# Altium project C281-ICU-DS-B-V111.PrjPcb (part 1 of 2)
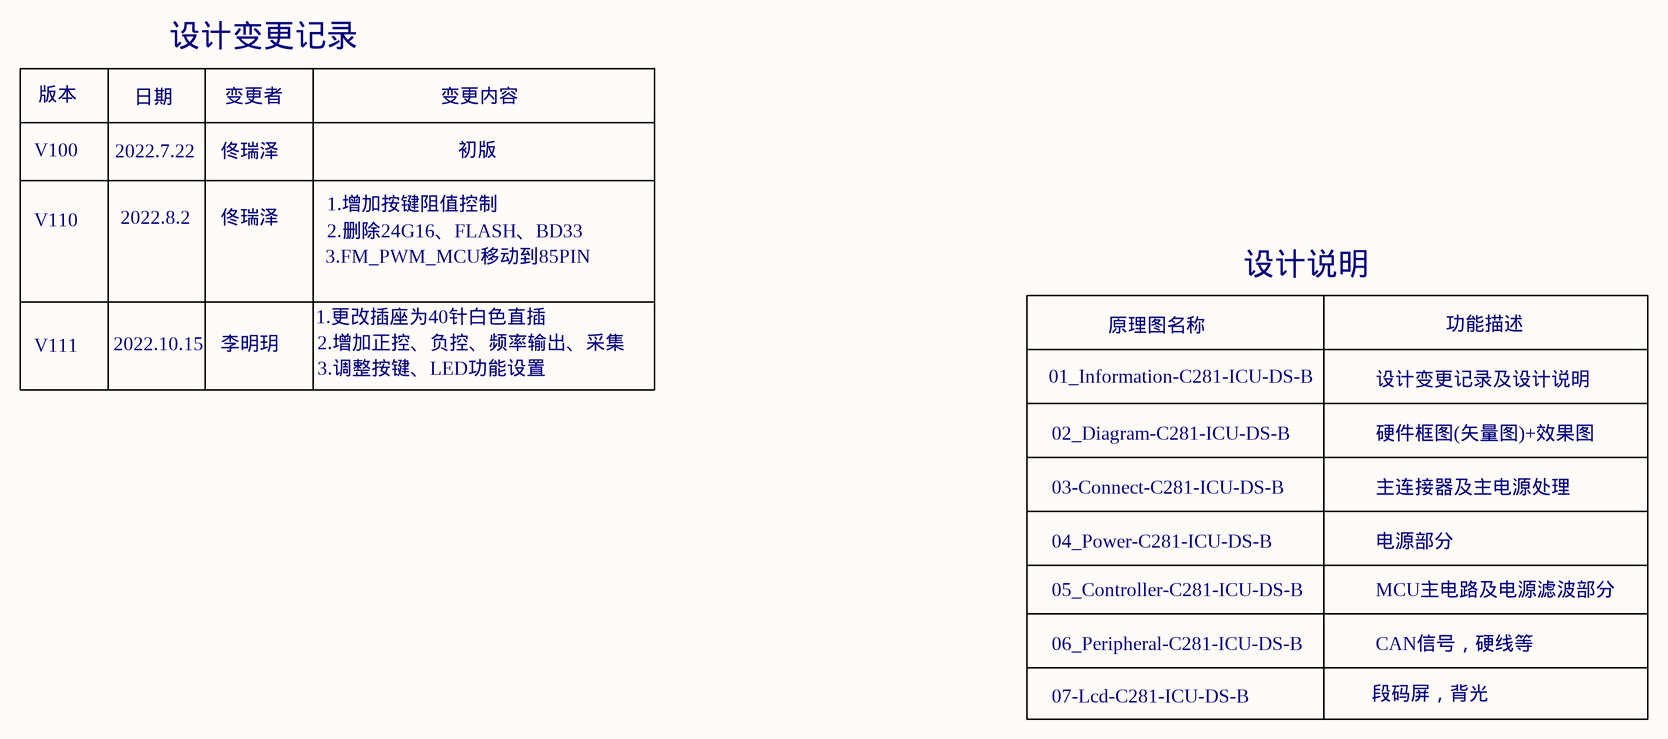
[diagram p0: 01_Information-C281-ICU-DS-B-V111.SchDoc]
7 sheets, 468 parts. Net scope: global (net labels, ports and power ports of the same name join across sheets).
Board file: C281-ICU-DS-B-V111.PcbDoc
Sheets:
  01_Information-C281-ICU-DS-B-V111.SchDoc
  02_Diagram-C281-ICU-DS-B-V111.SchDoc
  03_Connect-C281-ICU-DS-B-V111.SchDoc
  04_Power-C281-ICU-DS-B-V111.SchDoc
  05_Controller-C281-ICU-DS-B-V111.SchDoc
  06_Peripheral-C281-ICU-DS-B-V111.SchDoc
  07_Lcd-C281-ICU-DS-B-V111.SchDoc

## Sheet 01_Information-C281-ICU-DS-B-V111.SchDoc: C281-ICU-DS-B-V100
size A3; Date: 2022/07/22; DrawnBy: 佟瑞泽; DocumentNumber: 1; Revision: V100; SheetNumber: 1; SheetTotal: 7

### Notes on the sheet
- 设计变更记录
- 版本
- 日期
- 变更者
- 变更内容
- V100
- 2022.7.22
- 佟瑞泽
- 1.增加按键阻值控制
- 初版
- V110
- 2022.8.2
- 3.FM_PWM_MCU移动到85PIN
- 2.删除24G16、FLASH、BD33
- 设计说明
- 1.更改插座为40针白色直插
- 2.增加正控、负控、频率输出、采集
- 原理图名称
- 功能描述
- V111
- 2022.10.15
- 李明玥
- 3.调整按键、LED功能设置
- 01_Information-C281-ICU-DS-B
- 设计变更记录及设计说明
- 02_Diagram-C281-ICU-DS-B
- 硬件框图(矢量图)+效果图
- 03-Connect-C281-ICU-DS-B
- 04_Power-C281-ICU-DS-B
- 主连接器及主电源处理
- 电源部分
- 05_Controller-C281-ICU-DS-B
- MCU主电路及电源滤波部分
- 06_Peripheral-C281-ICU-DS-B
- CAN信号，硬线等
- 07-Lcd-C281-ICU-DS-B
- 段码屏，背光

## Sheet 02_Diagram-C281-ICU-DS-B-V111.SchDoc: C281-ICU-DS-B-V100
size A4; Date: 2022/07/22; DrawnBy: 佟瑞泽; DocumentNumber: 2; Revision: V100; SheetNumber: 2; SheetTotal: 7

## Sheet 03_Connect-C281-ICU-DS-B-V111.SchDoc: C281-ICU-DS-B-V100
size A4; Date: 2022/07/22; DrawnBy: 佟瑞泽; DocumentNumber: 3; Revision: V100; SheetNumber: 3; SheetTotal: 7
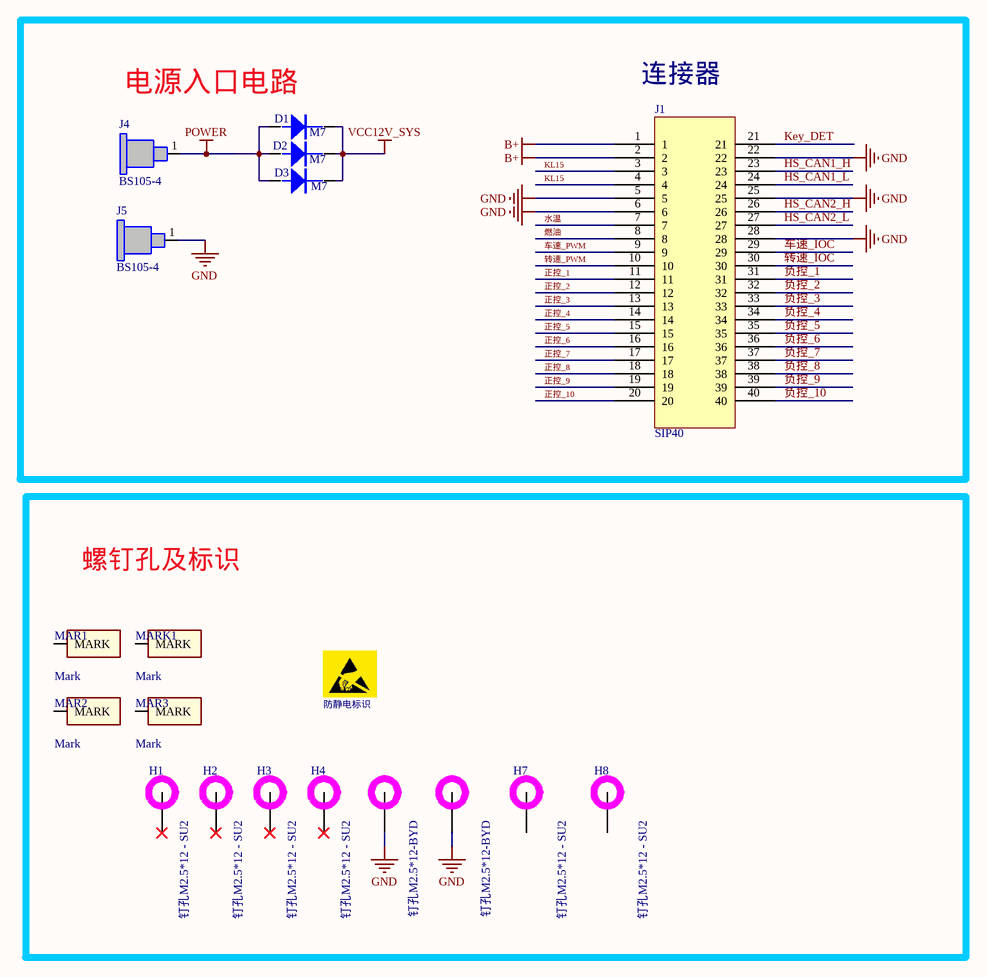
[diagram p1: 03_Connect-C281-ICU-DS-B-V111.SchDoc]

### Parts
D1  M7  [DO-214AC]
D2  M7  [DO-214AC]
D3  M7  [DO-214AC]
ESD1  ESD防静电标识  [ESD]  (value not drawn)  (no BOM)
H1  钉孔M2.5*12 - SU2  [钉孔M2.5*12 - SU2]  (no BOM)
H2  钉孔M2.5*12 - SU2  [钉孔M2.5*12 - SU2]  (no BOM)
H3  钉孔M2.5*12 - SU2  [钉孔M2.5*12 - SU2]  (no BOM)
H4  钉孔M2.5*12 - SU2  [钉孔M2.5*12 - SU2]  (no BOM)
H5  钉孔M2.5*12-BYD  [钉孔M2.5*12 - BYD]  (no BOM)
H6  钉孔M2.5*12-BYD  [钉孔M2.5*12 - BYD]  (no BOM)
H7  钉孔M2.5*12 - SU2  [钉孔M2.5*12 - SU2]  (no BOM)
H8  钉孔M2.5*12 - SU2  [钉孔M2.5*12 - SU2]  (no BOM)
J1  SIP40  [40P插座（白）]
J4  value BS105-4  [DIP-4MM]  (hidden comment: BS105-4-DIP)
J5  value BS105-4  [DIP-4MM]  (hidden comment: BS105-4-DIP)
MAR1  Mark  [MARK]  (no BOM)
MAR2  Mark  [MARK]  (no BOM)
MAR3  Mark  [MARK]  (no BOM)
MARK1  Mark  [MARK]  (no BOM)

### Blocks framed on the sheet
电源入口电路: D1-D3 J1 J4 J5
螺钉孔及标识: ESD1 H1-H8 MAR1-MAR3 MARK1

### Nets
B+: J1.1 J1.2
GND: H5.1 H6.1 J1.5 J1.6 J1.22 J1.25 J1.28 J5.1
KL15: J1.3 J1.4
POWER: D1.1 D2.1 D3.1 J4.1
VCC12V_SYS: D1.2 D2.2 D3.2
HS_CAN1_H: J1.23
HS_CAN1_L: J1.24
HS_CAN2_H: J1.26
HS_CAN2_L: J1.27
Key_DET: J1.21
正控_1: J1.11
正控_2: J1.12
正控_3: J1.13
正控_4: J1.14
正控_5: J1.15
正控_6: J1.16
正控_7: J1.17
正控_8: J1.18
正控_9: J1.19
正控_10: J1.20
水温: J1.7
燃油: J1.8
负控_1: J1.31
负控_2: J1.32
负控_3: J1.33
负控_4: J1.34
负控_5: J1.35
负控_6: J1.36
负控_7: J1.37
负控_8: J1.38
负控_9: J1.39
负控_10: J1.40
车速_IOC: J1.29
车速_PWM: J1.9
转速_IOC: J1.30
转速_PWM: J1.10

Not connected (* = marked no-connect by the designer): H1 1*; H2 1*; H3 1*; H4 1*; H7 1; H8 1; MAR1 1(MARK); MAR2 1(MARK); MAR3 1(MARK); MARK1 1(MARK)

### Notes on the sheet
- 连接器

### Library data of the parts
D1-D3 = M7: Diode,Vr=1000V,If=1.0A,Vf=1.1V,DO-214AC,M7,5.26*2.79*0.9mm; Part Number: 30307015; Manufacture 1: 深圳西龙; 代理/分销商: 深圳市长江电子有限公司
ESD1 = ESD防静电标识: 防静电标识
H1-H4 H7 H8 = 钉孔M2.5*12 - SU2: 适配M2.5*12螺钉
H5 H6 = 钉孔M2.5*12-BYD: 适配 M2.5*12 螺钉(钉帽直径6mm)
J1 = SIP40: Connector,单排针,PITCH=2.54mm,40PIN,DIP,直插,立式; Manufacture 1 P/N: 插座40针直; Part Number: 30401004; 代理/分销商: 深圳市国天电子股份有限公司
J4 J5 = BS105-4-DIP: Connector,4mm香蕉插头插座,H=28mm,DIP
MAR1-MAR3 MARK1 = Mark: MARK点

## Sheet 04_Power-C281-ICU-DS-B-V111.SchDoc: C281-ICU-DS-B-V100
size A4; Date: 2022/07/22; DrawnBy: 佟瑞泽; DocumentNumber: 4; Revision: V100; SheetNumber: 4; SheetTotal: 7
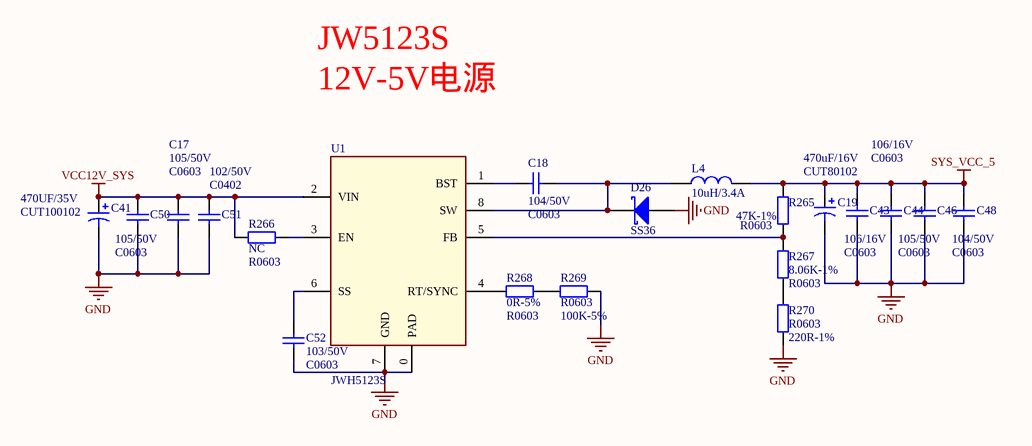
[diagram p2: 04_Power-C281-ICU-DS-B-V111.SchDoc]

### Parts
C17  value 105/50V  [C0603]  (hidden comment: 105-50V)
C18  value 104/50V  [C0603]  (hidden comment: 104)
C19  value 470uF/16V  [CUT80102]  (hidden comment: 470uF-16V)
C41  value 470UF/35V  [CUT100102]  (hidden comment: 470uF-35V)
C43  value 106/16V  [C0603]  (hidden comment: 106-16V)
C44  value 106/16V  [C0603]  (hidden comment: 106-16V)
C46  value 105/50V  [C0603]  (hidden comment: 105-50V)
C48  value 104/50V  [C0603]  (hidden comment: 104)
C50  value 105/50V  [C0603]  (hidden comment: 105-50V)
C51  value 102/50V  [C0402]  (hidden comment: 102-50V)
C52  value 103/50V  [C0603]  (hidden comment: 103)
D26  SS36  [DO-214AB]
L4  value 10uH/3.4A  [VLS6045EX]  (hidden comment: 6045EX-100M-H)
R265  value 47K-1%  [R0603]  (hidden comment: 47K-J)
R266  NC  [R0603]
R267  value 8.06K-1%  [R0603]  (hidden comment: 8.06K-J)
R268  value 0R-5%  [R0603]  (hidden comment: 0R)
R269  value 100K-5%  [R0603]  (hidden comment: 100K)
R270  value 220R-1%  [R0603]  (hidden comment: 220R-J)
U1  JWH5123S  [ESOP8]

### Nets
GND: C17.1 C19.2 C41.2 C43.1 C44.1 C46.1 C48.1 C50.1 C51.1 C52.1 D26.1(A) R269.2 R270.1 U1.0(PAD) U1.7(GND)
SYS_VCC_5: C19.1 C43.2 C44.2 C46.2 C48.2 L4.2 R265.2
VCC12V_SYS: C17.2 C41.1 C50.2 C51.2 R266.1 U1.2(VIN)
NetC18_1: C18.1 D26.2(K) L4.1 U1.8(SW)
NetC18_2: C18.2 U1.1(BST)
NetC52_2: C52.2 U1.6(SS)
NetR265_1: R265.1 R267.2 U1.5(FB)
NetR266_2: R266.2 U1.3(EN)
NetR267_1: R267.1 R270.2
NetR268_1: R268.1 U1.4(RT/SYNC)
NetR268_2: R268.2 R269.1

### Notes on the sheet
- 12V-5V电源
- JW5123S

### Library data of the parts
C17 C46 C50 = C105-50V-C0603-X: CAP,105,50V,10%,C0603; Part Number: 30305198; Manufacture 1: YAGEO; Manufacture 1 P/N: CL10A105KB8NNNC; 代理/分销商: 厦门信和达电子有限公司; 元件名称: 贴片电容105-0603-50V X
C18 C48 = C104-50V-C0603-X: CAP,104,50V,10%,,C0603; Part Number: 30305248; Manufacture 1 P/N: CC0603KRX7R9BB104; 代理/分销商: 厦门信和达电子有限公司; 元件名称: 贴片电容104-0603-50V X
C19 = C470UF-16V-CUT80102: ECAP,470uF,16V,20%,φ8x10.2mm,SMD; Part Number: 30311002; Manufacture 1: KS; Manufacture 1 P/N: CS16V470UF; 代理/分销商: 北京圣基工贸公司/广东东联盛科技有限公司/东莞市柯森奥泰科技有限公司; 元件名称: 贴片电解16V470
C41 = C470uF-35V-CUT100102: ECAP,470uF,35V,20%,φ10x10.2mm,SMD; Part Number: 30311004; Manufacture 1: KS; Manufacture 1 P/N: CS35V470UF; 代理/分销商: 北京圣基工贸公司/广东东联盛科技有限公司/东莞市柯森奥泰科技有限公司; 元件名称: 贴片电解35V470
C43 C44 = C106-16V-C0603-X: CAP,106,16V,20%,C0603; Part Number: 30305207; Manufacture 1: YAGEO; Manufacture 1 P/N: CC0603MRX5R7BB106; 代理/分销商: 厦门信和达电子有限公司; 元件名称: 贴片电容106-0603-16V X
C51 = C102-50V-C0402-X: CAP,102,50V,10%,C0402; Part Number: 30305215; Manufacture 1: YAGEO; Manufacture 1 P/N: CC0402KRX7R9BB102; 代理/分销商: 厦门信和达电子有限公司; 元件名称: 贴片电容102-0402-50V X
C52 = C103-50V-C0603-X: CAP,103,50V,10%,C0603; Part Number: 30305245; Manufacture 1: YAGEO; Manufacture 1 P/N: CC0603KRX7R9BB103; 代理/分销商: 厦门信和达电子有限公司; 元件名称: 贴片电容103-0603-50V X
D26 = SS36: Diode,Vr=60V,If=3A,Vf=0.75V,DO-214AB,SS36,6.22*8.13*2.62mm; Part Number: 30307090; Manufacture 1: GENERAL SEMICONDUCTOR; 代理/分销商: 四平市吉华高新技术有限公司; 元件名称: 肖特基二极管SS36
L4 = VLS6045EX-100M-H: Inductor,10uH±20%,3.9AIsat),3.4A(Itemp),6.3*6*4.5mm; Part Number: 30310059; Manufacture 1: TDK; 代理/分销商: 创思（北京）电子技术有限公司; 元件名称: VLS6045EX-100M-H  10UH电感（车规级）
R265 = R47K_0603_1%: RES,47K,1/10W,1%,R0603; Part Number: 30304413; Manufacture 1: 风华高科FH; Manufacture 1 P/N: RS03K4702FT; 代理/分销商: 四平市吉华高新技术有限公司; 元件名称: 贴片电阻47KΩ-精密-0603
R266 = R_NC_0603: RES,R0603; 元件名称: 贴片电阻NC-0603
R267 = R8.06K_0603_1%_X: RES,8.06K,1/10W,1%,R0603; Part Number: 30304398; Manufacture 1: YAGEO; Manufacture 1 P/N: RC0603FR-078K06L; 代理/分销商: 厦门信和达电子有限公司; 元件名称: 贴片电阻8.06K-0603-精密 X
R268 = R0R_0603_5%_X: RES,0R,1/10W,5%,R0603; Part Number: 30304421; Manufacture 1: YAGEO; Manufacture 1 P/N: RC0603JR-070RL; 代理/分销商: 厦门信和达电子有限公司; 元件名称: 贴片电阻0Ω-0603 X
R269 = R100K_0603_5%_X: RES,100K,1/10W,5%,R0603; Part Number: 30304410; Manufacture 1: YAGEO; Manufacture 1 P/N: RC0603JR-07100KL; 代理/分销商: 厦门信和达电子有限公司; 元件名称: 贴片电阻100K-0603 X
R270 = R220R_0603_1%_X: RES,220R,1/10W,1%,R0603; Part Number: 30304392; Manufacture 1: YAGEO; Manufacture 1 P/N: RC0603FR-07220RL; 代理/分销商: 厦门信和达电子有限公司; 元件名称: 贴片电阻220Ω-0603-精密 X
U1 = JWH5123S: IC,JWH5123S,DCDC,ESOP-8,6x4.9x1.5mm,-40~125℃; Part Number: 30301464; Manufacture 1: JWJOULWATT; Manufacture 1 P/N: JWH5123SESOP#TRPBF; 备注: 电源芯片JW5123; 代理/分销商: 大联大商贸有限公司

## Sheet 05_Controller-C281-ICU-DS-B-V111.SchDoc: C281-ICU-DS-B-V100
size A2; Date: 2022/07/22; DrawnBy: 佟瑞泽; Organization: Protel International P/L; DocumentNumber: 5; Revision: V100; SheetNumber: 5; SheetTotal: 7
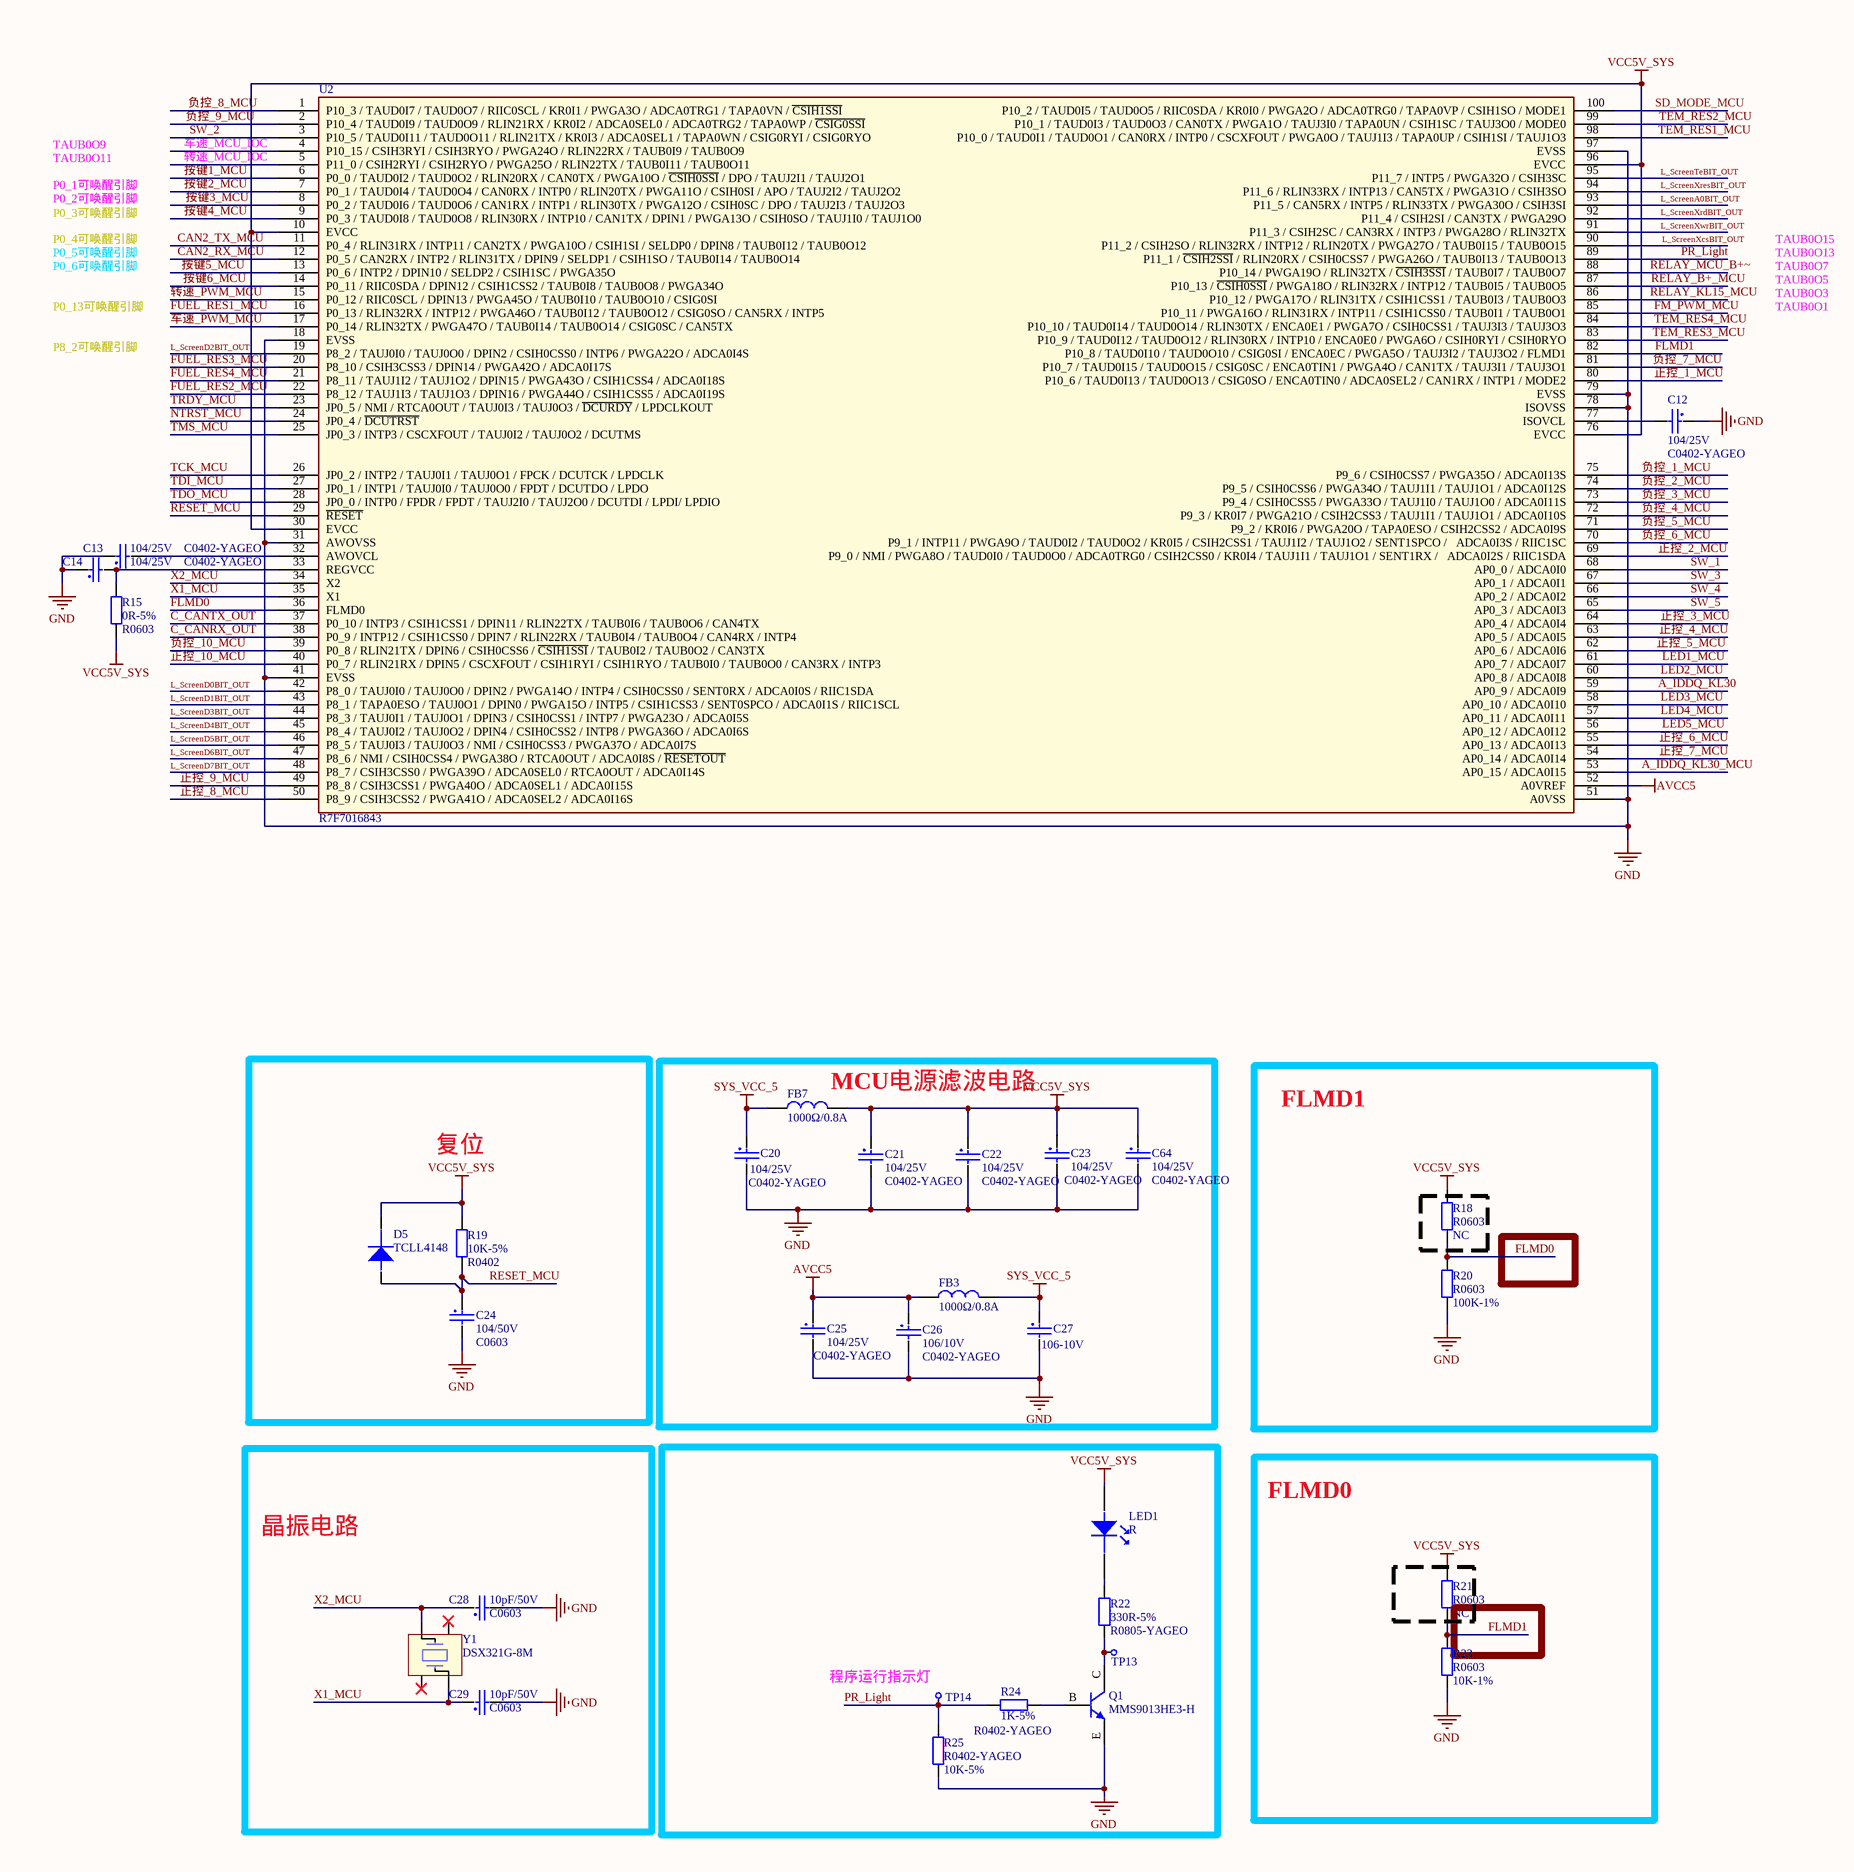
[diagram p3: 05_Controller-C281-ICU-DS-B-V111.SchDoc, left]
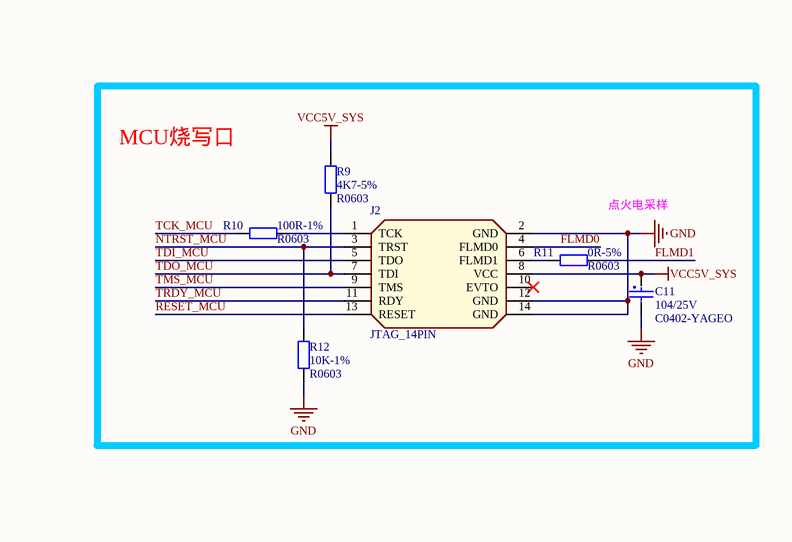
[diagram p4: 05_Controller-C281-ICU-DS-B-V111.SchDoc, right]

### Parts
C11  value 104/25V  [C0402-YAGEO]  (hidden comment: 104-25V)
C12  value 104/25V  [C0402-YAGEO]  (hidden comment: 104-25V)
C13  value 104/25V  [C0402-YAGEO]  (hidden comment: 104-25V)
C14  value 104/25V  [C0402-YAGEO]  (hidden comment: 104-25V)
C20  value 104/25V  [C0402-YAGEO]  (hidden comment: 104-25V)
C21  value 104/25V  [C0402-YAGEO]  (hidden comment: 104-25V)
C22  value 104/25V  [C0402-YAGEO]  (hidden comment: 104-25V)
C23  value 104/25V  [C0402-YAGEO]  (hidden comment: 104-25V)
C24  value 104/50V  Footprint: C0603  [C0603-YAGEO]  (hidden comment: 104)
C25  value 104/25V  [C0402-YAGEO]  (hidden comment: 104-25V)
C26  value 106/10V  [C0402-YAGEO]  (hidden comment: 106-10V)
C27  106-10V  [C0402-YAGEO]
C28  value 10pF/50V  [C0603]  (hidden comment: 10pF)
C29  value 10pF/50V  [C0603]  (hidden comment: 10pF)
C64  value 104/25V  [C0402-YAGEO]  (hidden comment: 104-25V)
D5  value TCLL4148  [4148-A]  (hidden comment: 4148)
FB3  value 1000Ω/0.8A  [BLM18PG600SH1]  (hidden comment: 1000@100MHz)
FB7  value 1000Ω/0.8A  [BLM18PG600SH1]  (hidden comment: 1000@100MHz)
J2  value JTAG_14PIN  [JTAG-14PIN]  (hidden comment: JTAG_14)
LED1  R  [LED]
Q1  MMS9013HE3-H  [SOT-23]
R9  value 4K7-5%  Footprint: R0603  [R0603-YAGEO]  (hidden comment: 4K7)
R10  100R-1%  [R0603]
R11  value 0R-5%  Footprint: R0603  [R0603-YAGEO]  (hidden comment: 0R)
R12  value 10K-1%  Footprint: R0603  [R0603-YAGEO]  (hidden comment: 10K-J)
R15  value 0R-5%  [R0603]  (hidden comment: 0R)
R18  NC  [R0603]
R19  value 10K-5%  Footprint: R0402  [R0402-YAGEO]  (hidden comment: 10K)
R20  value 100K-1%  Footprint: R0603  [R0603-YAGEO]  (hidden comment: 100K-J)
R21  NC  [R0603]
R22  value 330R-5%  [R0805-YAGEO]  (hidden comment: 330R)
R23  value 10K-1%  Footprint: R0603  [R0603-YAGEO]  (hidden comment: 10K-J)
R24  value 1K-5%  [R0402-YAGEO]  (hidden comment: 1K)
R25  value 10K-5%  [R0402-YAGEO]  (hidden comment: 10K)
TP13  1.0测试点  [TP1.0]  (value not drawn)
TP14  1.0测试点  [TP1.0]  (value not drawn)
U2  R7F7016843  [P-LFQFP100]
Y1  value DSX321G-8M  [Crystal3225]  (hidden comment: 8M)

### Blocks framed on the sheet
MCU烧写口: C11 J2 R9-R12
复位: C24 D5 R19
MCU电源滤波电路: C20-C23 C25-C27 C64 FB3 FB7
FLMD1: R18 R20
晶振电路: C28 C29 Y1
程序运行指示灯: LED1 Q1 R22 R24 R25 TP13 TP14
FLMD0: R21 R23

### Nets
AVCC5: C25.1 C26.1 FB3.1 U2.52(A0VREF)
GND: C11.2 C12.1 C13.1 C14.1 C20.2 C21.2 C22.2 C23.2 C24.2 C25.2 C26.2 C27.2 C28.2 C29.2 C64.2 J2.2(GND) J2.12(GND) J2.14(GND) Q1.E R12.2 R20.1 R23.1 R25.1 U2.18(EVSS) U2.31(AWOVSS) U2.41(EVSS) U2.51(A0VSS) U2.78(ISOVSS) U2.79(EVSS) U2.97(EVSS)
SYS_VCC_5: C20.1 C27.1 FB3.2 FB7.1
VCC5V_SYS: C11.1 C21.1 C22.1 C23.1 C64.1 D5.2 FB7.2 J2.8(VCC) LED1.1 R9.1 R15.1 R18.2 R19.2 R21.2 U2.10(EVCC) U2.30(EVCC) U2.76(EVCC) U2.96(EVCC)
A_IDDQ_KL30: U2.59(AP0_9_/_ADCA0I9)
A_IDDQ_KL30_MCU: U2.53(AP0_15_/_ADCA0I15)
C_CANRX_OUT: U2.38(P0_9_/_INTP12_/_CSIH1CSS0_/_DPIN7_/_RLIN22RX_/_TAUB0I4_/_TAUB0O4_/_CAN4RX_/_INTP4)
C_CANTX_OUT: U2.37(P0_10_/_INTP3_/_CSIH1CSS1_/_DPIN11_/_RLIN22TX_/_TAUB0I6_/_TAUB0O6_/_CAN4TX)
CAN2_RX_MCU: U2.12(P0_5_/_CAN2RX_/_INTP2_/_RLIN31TX_/_DPIN9_/_SELDP1_/_CSIH1SO_/_TAUB0I14_/_TAUB0O14)
CAN2_TX_MCU: U2.11(P0_4_/_RLIN31RX_/_INTP11_/_CAN2TX_/_PWGA10O_/_CSIH1SI_/_SELDP0_/_DPIN8_/_TAUB0I12_/_TAUB0O12)
FLMD0: J2.4(FLMD0) R18.1 R20.2 U2.36(FLMD0)
FLMD1: R11.2 R21.1 R23.2 U2.82(P10_8_/_TAUD0I10_/_TAUD0O10_/_CSIG0SI_/_ENCA0EC_/_PWGA5O_/_TAUJ3I2_/_TAUJ3O2_/_FLMD1)
FM_PWM_MCU: U2.85(P10_11_/_PWGA16O_/_RLIN31RX_/_INTP11_/_CSIH1CSS0_/_TAUB0I1_/_TAUB0O1)
FUEL_RES1_MCU: U2.16(P0_13_/_RLIN32RX_/_INTP12_/_PWGA46O_/_TAUB0I12_/_TAUB0O12_/_CSIG0SO_/_CAN5RX_/_INTP5)
FUEL_RES2_MCU: U2.22(P8_12_/_TAUJ1I3_/_TAUJ1O3_/_DPIN16_/_PWGA44O_/_CSIH1CSS5_/_ADCA0I19S)
FUEL_RES3_MCU: U2.20(P8_10_/_CSIH3CSS3_/_DPIN14_/_PWGA42O_/_ADCA0I17S)
FUEL_RES4_MCU: U2.21(P8_11_/_TAUJ1I2_/_TAUJ1O2_/_DPIN15_/_PWGA43O_/_CSIH1CSS4_/_ADCA0I18S)
L_ScreenA0BIT_OUT: U2.93(P11_5_/_CAN5RX_/_INTP5_/_RLIN33TX_/_PWGA30O_/_CSIH3SI)
L_ScreenD0BIT_OUT: U2.42(P8_0_/_TAUJ0I0_/_TAUJ0O0_/_DPIN2_/_PWGA14O_/_INTP4_/_CSIH0CSS0_/_SENT0RX_/_ADCA0I0S_/_RIIC1SDA)
L_ScreenD1BIT_OUT: U2.43(P8_1_/_TAPA0ESO_/_TAUJ0O1_/_DPIN0_/_PWGA15O_/_INTP5_/_CSIH1CSS3_/_SENT0SPCO_/_ADCA0I1S_/_RIIC1SCL)
L_ScreenD2BIT_OUT: U2.19(P8_2_/_TAUJ0I0_/_TAUJ0O0_/_DPIN2_/_CSIH0CSS0_/_INTP6_/_PWGA22O_/_ADCA0I4S)
L_ScreenD3BIT_OUT: U2.44(P8_3_/_TAUJ0I1_/_TAUJ0O1_/_DPIN3_/_CSIH0CSS1_/_INTP7_/_PWGA23O_/_ADCA0I5S)
L_ScreenD4BIT_OUT: U2.45(P8_4_/_TAUJ0I2_/_TAUJ0O2_/_DPIN4_/_CSIH0CSS2_/_INTP8_/_PWGA36O_/_ADCA0I6S)
L_ScreenD5BIT_OUT: U2.46(P8_5_/_TAUJ0I3_/_TAUJ0O3_/_NMI_/_CSIH0CSS3_/_PWGA37O_/_ADCA0I7S)
L_ScreenD6BIT_OUT: U2.47(P8_6_/_NMI_/_CSIH0CSS4_/_PWGA38O_/_RTCA0OUT_/_ADCA0I8S_/_~{RESETOUT})
L_ScreenD7BIT_OUT: U2.48(P8_7_/_CSIH3CSS0_/_PWGA39O_/_ADCA0SEL0_/_RTCA0OUT_/_ADCA0I14S)
L_ScreenTeBIT_OUT: U2.95(P11_7_/_INTP5_/_PWGA32O_/_CSIH3SC)
L_ScreenXcsBIT_OUT: U2.90(P11_2_/_CSIH2SO_/_RLIN32RX_/_INTP12_/_RLIN20TX_/_PWGA27O_/_TAUB0I15_/_TAUB0O15)
L_ScreenXrdBIT_OUT: U2.92(P11_4_/_CSIH2SI_/_CAN3TX_/_PWGA29O)
L_ScreenXresBIT_OUT: U2.94(P11_6_/_RLIN33RX_/_INTP13_/_CAN5TX_/_PWGA31O_/_CSIH3SO)
L_ScreenXwrBIT_OUT: U2.91(P11_3_/_CSIH2SC_/_CAN3RX_/_INTP3_/_PWGA28O_/_RLIN32TX)
LED1_MCU: U2.61(AP0_7_/_ADCA0I7)
LED2_MCU: U2.60(AP0_8_/_ADCA0I8)
LED3_MCU: U2.58(AP0_10_/_ADCA0I10)
LED4_MCU: U2.57(AP0_11_/_ADCA0I11)
LED5_MCU: U2.56(AP0_12_/_ADCA0I12)
NTRST_MCU: J2.3(TRST) R12.1 U2.24(JP0_4_/_~{DCUTRST})
PR_Light: R24.2 R25.2 TP14.1 U2.89(P11_1_/_~{CSIH2SSI}_/_RLIN20RX_/_CSIH0CSS7_/_PWGA26O_/_TAUB0I13_/_TAUB0O13)
RELAY_B+_MCU: U2.87(P10_13_/_~{CSIH0SSI}_/_PWGA18O_/_RLIN32RX_/_INTP12_/_TAUB0I5_/_TAUB0O5)
RELAY_KL15_MCU: U2.86(P10_12_/_PWGA17O_/_RLIN31TX_/_CSIH1CSS1_/_TAUB0I3_/_TAUB0O3)
RELAY_MCU_B+~: U2.88(P10_14_/_PWGA19O_/_RLIN32TX_/_~{CSIH3SSI}_/_TAUB0I7_/_TAUB0O7)
RESET_MCU: C24.1 D5.1 J2.13(RESET) R19.1 U2.29(~{RESET})
SD_MODE_MCU: U2.100(P10_2_/_TAUD0I5_/_TAUD0O5_/_RIIC0SDA_/_KR0I0_/_PWGA2O_/_ADCA0TRG0_/_TAPA0VP_/_CSIH1SO_/_MODE1)
SW_1: U2.68(AP0_0_/_ADCA0I0)
SW_2: U2.3(P10_5_/_TAUD0I11_/_TAUD0O11_/_RLIN21TX_/_KR0I3_/_ADCA0SEL1_/_TAPA0WN_/_CSIG0RYI_/_CSIG0RYO)
SW_3: U2.67(AP0_1_/_ADCA0I1)
SW_4: U2.66(AP0_2_/_ADCA0I2)
SW_5: U2.65(AP0_3_/_ADCA0I3)
TCK_MCU: R10.1 U2.26(JP0_2_/_INTP2_/_TAUJ0I1_/_TAUJ0O1_/_FPCK_/_DCUTCK_/_LPDCLK)
TDI_MCU: J2.5(TDO) U2.27(JP0_1_/_INTP1_/_TAUJ0I0_/_TAUJ0O0_/_FPDT_/_DCUTDO_/_LPDO)
TDO_MCU: J2.7(TDI) R9.2 U2.28(JP0_0_/_INTP0_/_FPDR_/_FPDT_/_TAUJ2I0_/_TAUJ2O0_/_DCUTDI_/_LPDI/_LPDIO)
TEM_RES1_MCU: U2.98(P10_0_/_TAUD0I1_/_TAUD0O1_/_CAN0RX_/_INTP0_/_CSCXFOUT_/_PWGA0O_/_TAUJ1I3_/_TAPA0UP_/_CSIH1SI_/_TAUJ1O3)
TEM_RES2_MCU: U2.99(P10_1_/_TAUD0I3_/_TAUD0O3_/_CAN0TX_/_PWGA1O_/_TAUJ3I0_/_TAPA0UN_/_CSIH1SC_/_TAUJ3O0_/_MODE0)
TEM_RES3_MCU: U2.83(P10_9_/_TAUD0I12_/_TAUD0O12_/_RLIN30RX_/_INTP10_/_ENCA0E0_/_PWGA6O_/_CSIH0RYI_/_CSIH0RYO)
TEM_RES4_MCU: U2.84(P10_10_/_TAUD0I14_/_TAUD0O14_/_RLIN30TX_/_ENCA0E1_/_PWGA7O_/_CSIH0CSS1_/_TAUJ3I3_/_TAUJ3O3)
TMS_MCU: J2.9(TMS) U2.25(JP0_3_/_INTP3_/_CSCXFOUT_/_TAUJ0I2_/_TAUJ0O2_/_DCUTMS)
TRDY_MCU: J2.11(RDY) U2.23(JP0_5_/_NMI_/_RTCA0OUT_/_TAUJ0I3_/_TAUJ0O3_/_~{DCURDY}_/_LPDCLKOUT)
X1_MCU: C29.1 U2.35(X1) Y1.1
X2_MCU: C28.1 U2.34(X2) Y1.3
按键1_MCU: U2.6(P0_0_/_TAUD0I2_/_TAUD0O2_/_RLIN20RX_/_CAN0TX_/_PWGA10O_/_~{CSIH0SSI}_/_DPO_/_TAUJ2I1_/_TAUJ2O1)
按键2_MCU: U2.7(P0_1_/_TAUD0I4_/_TAUD0O4_/_CAN0RX_/_INTP0_/_RLIN20TX_/_PWGA11O_/_CSIH0SI_/_APO_/_TAUJ2I2_/_TAUJ2O2)
按键3_MCU: U2.8(P0_2_/_TAUD0I6_/_TAUD0O6_/_CAN1RX_/_INTP1_/_RLIN30TX_/_PWGA12O_/_CSIH0SC_/_DPO_/_TAUJ2I3_/_TAUJ2O3)
按键4_MCU: U2.9(P0_3_/_TAUD0I8_/_TAUD0O8_/_RLIN30RX_/_INTP10_/_CAN1TX_/_DPIN1_/_PWGA13O_/_CSIH0SO_/_TAUJ1I0_/_TAUJ1O0)
按键5_MCU: U2.13(P0_6_/_INTP2_/_DPIN10_/_SELDP2_/_CSIH1SC_/_PWGA35O)
按键6_MCU: U2.14(P0_11_/_RIIC0SDA_/_DPIN12_/_CSIH1CSS2_/_TAUB0I8_/_TAUB0O8_/_PWGA34O)
正控_1_MCU: U2.80(P10_6_/_TAUD0I13_/_TAUD0O13_/_CSIG0SO_/_ENCA0TIN0_/_ADCA0SEL2_/_CAN1RX_/_INTP1_/_MODE2)
正控_2_MCU: U2.69(P9_0_/_NMI_/_PWGA8O_/_TAUD0I0_/_TAUD0O0_/_ADCA0TRG0_/_CSIH2CSS0_/_KR0I4_/_TAUJ1I1_/_TAUJ1O1_/_SENT1RX_/___ADCA0I2S_/_RIIC1SDA)
正控_3_MCU: U2.64(AP0_4_/_ADCA0I4)
正控_4_MCU: U2.63(AP0_5_/_ADCA0I5)
正控_5_MCU: U2.62(AP0_6_/_ADCA0I6)
正控_6_MCU: U2.55(AP0_13_/_ADCA0I13)
正控_7_MCU: U2.54(AP0_14_/_ADCA0I14)
正控_8_MCU: U2.50(P8_9_/_CSIH3CSS2_/_PWGA41O_/_ADCA0SEL2_/_ADCA0I16S)
正控_9_MCU: U2.49(P8_8_/_CSIH3CSS1_/_PWGA40O_/_ADCA0SEL1_/_ADCA0I15S)
正控_10_MCU: U2.40(P0_7_/_RLIN21RX_/_DPIN5_/_CSCXFOUT_/_CSIH1RYI_/_CSIH1RYO_/_TAUB0I0_/_TAUB0O0_/_CAN3RX_/_INTP3)
负控_1_MCU: U2.75(P9_6_/_CSIH0CSS7_/_PWGA35O_/_ADCA0I13S)
负控_2_MCU: U2.74(P9_5_/_CSIH0CSS6_/_PWGA34O_/_TAUJ1I1_/_TAUJ1O1_/_ADCA0I12S)
负控_3_MCU: U2.73(P9_4_/_CSIH0CSS5_/_PWGA33O_/_TAUJ1I0_/_TAUJ1O0_/_ADCA0I11S)
负控_4_MCU: U2.72(P9_3_/_KR0I7_/_PWGA21O_/_CSIH2CSS3_/_TAUJ1I1_/_TAUJ1O1_/_ADCA0I10S)
负控_5_MCU: U2.71(P9_2_/_KR0I6_/_PWGA20O_/_TAPA0ESO_/_CSIH2CSS2_/_ADCA0I9S)
负控_6_MCU: U2.70(P9_1_/_INTP11_/_PWGA9O_/_TAUD0I2_/_TAUD0O2_/_KR0I5_/_CSIH2CSS1_/_TAUJ1I2_/_TAUJ1O2_/_SENT1SPCO_/___ADCA0I3S_/_RIIC1SC)
负控_7_MCU: U2.81(P10_7_/_TAUD0I15_/_TAUD0O15_/_CSIG0SC_/_ENCA0TIN1_/_PWGA4O_/_CAN1TX_/_TAUJ3I1_/_TAUJ3O1)
负控_8_MCU: U2.1(P10_3_/_TAUD0I7_/_TAUD0O7_/_RIIC0SCL_/_KR0I1_/_PWGA3O_/_ADCA0TRG1_/_TAPA0VN_/_~{CSIH1SSI})
负控_9_MCU: U2.2(P10_4_/_TAUD0I9_/_TAUD0O9_/_RLIN21RX_/_KR0I2_/_ADCA0SEL0_/_ADCA0TRG2_/_TAPA0WP_/_~{CSIG0SSI})
负控_10_MCU: U2.39(P0_8_/_RLIN21TX_/_DPIN6_/_CSIH0CSS6_/_~{CSIH1SSI}_/_TAUB0I2_/_TAUB0O2_/_CAN3TX)
车速_MCU_IOC: U2.4(P10_15_/_CSIH3RYI_/_CSIH3RYO_/_PWGA24O_/_RLIN22RX_/_TAUB0I9_/_TAUB0O9)
车速_PWM_MCU: U2.17(P0_14_/_RLIN32TX_/_PWGA47O_/_TAUB0I14_/_TAUB0O14_/_CSIG0SC_/_CAN5TX)
转速_MCU_IOC: U2.5(P11_0_/_CSIH2RYI_/_CSIH2RYO_/_PWGA25O_/_RLIN22TX_/_TAUB0I11_/_TAUB0O11)
转速_PWM_MCU: U2.15(P0_12_/_RIIC0SCL_/_DPIN13_/_PWGA45O_/_TAUB0I10_/_TAUB0O10_/_CSIG0SI)
NetC12_2: C12.2 U2.77(ISOVCL)
NetC13_2: C13.2 U2.32(AWOVCL)
NetC14_2: C14.2 R15.2 U2.33(REGVCC)
NetJ2_1: J2.1(TCK) R10.2
NetJ2_6: J2.6(FLMD1) R11.1
NetLED1_2: LED1.2 R22.2
NetQ1_B: Q1.B R24.1
NetQ1_C: Q1.C R22.1 TP13.1

Not connected (* = marked no-connect by the designer): J2 10(EVTO)*; Y1 2* 4*

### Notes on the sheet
- 点火电采样
- Labels drawn without touching a wire or pin: P0_1可唤醒引脚, P0_2可唤醒引脚, P0_3可唤醒引脚, P0_4可唤醒引脚, P0_5可唤醒引脚, P0_6可唤醒引脚, P0_13可唤醒引脚, P8_2可唤醒引脚, TAUB0O1, TAUB0O3, TAUB0O5, TAUB0O7, TAUB0O9, TAUB0O11, TAUB0O13, TAUB0O15

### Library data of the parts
C11-C14 C20-C23 C25 C64 = C104-25V-C0402-X: CAP,104,25V,10%,C0402; Part Number: 30305217; Manufacture 1: YAGEO; Manufacture 1 P/N: CC0402KRX7R8BB104; 代理/分销商: 厦门信和达电子有限公司
C24 = C104-50V-C0603-X: CAP,104,50V,10%,C0603; Part Number: 30305248; Manufacture 1: YAGEO; Manufacture 1 P/N: CC0603KRX7R9BB104; 代理/分销商: 厦门信和达电子有限公司
C26 C27 = C106-10V-C0402-X: CAP,106,10V,10%,C0402; Part Number: 30305214; Manufacture 1: YAGEO; Manufacture 1 P/N: CC0402MRX5R6BB106; 代理/分销商: 厦门信和达电子有限公司
C28 C29 = C10pF-50V-C0603-X: CAP,10pF,50V,5%,C0603; Part Number: 30305257; Manufacture 1: YAGEO; Manufacture 1 P/N: CC0603JRNPO9BN100; 代理/分销商: 厦门信和达电子有限公司
D5 = 1N4148: Diode,If=10mA@Vf=1.0V,Wiv=75V,DO213AC,TCLL4148; Part Number: 30307014; Manufacture 1: TAK CHEONG; 代理/分销商: 深圳市长江电子有限公司
FB3 FB7 = 1000Ω/0.8A-AEC-Q200: Bead,1000Ω@100MHz,25%,0.8A,1.6x0.8x0.8mm; Part Number: 30319012; Manufacture 1: TDK; Manufacture 1 P/N: MPZ1608S102ATD25; 代理/分销商: 创思（北京）电子技术有限公司
J2 = JTAG_14PIN: Connector,双排针,PITCH=2.54mm,14PIN,SMD
LED1 = LED-R: LED,普通红; Part Number: 30303001
Q1 = MMS9013HE3-H: NPN,Vcbo=40V,Vceo=25V,Vebo=5V,IC=0.5A,SOT-23,3.04*1.4*1.1mm; Manufacture 1: MCC美微科; Part Number: 30306023
R9 = R4K7_0603_5%_X: RES,4K7,1/10W,5%,R0603; Part Number: 30304414; Manufacture 1: YAGEO; Manufacture 1 P/N: RC0603JR-074K7L; 代理/分销商: 厦门信和达电子有限公司; 元件名称: 贴片电阻4.7K-0603 X
R10 = R100R_0603_1%: RES,100R,1/10W,1%,R0603; Manufacture 1: 风华高科FH; Manufacture 1 P/N: RS03K101JT; 代理/分销商: 四平市吉华高新技术有限公司
R11 = R0R_0603_5%_X: as R268 on sheet 04_Power-C281-ICU-DS-B-V111
R12 R23 = R10K_0603_1%_X: RES,10K,1/10W,1%,R0603; Part Number: 30304383; Manufacture 1: YAGEO; Manufacture 1 P/N: RC0603FR-0710KL; 代理/分销商: 厦门信和达电子有限公司; 元件名称: 贴片电阻10K-0603-精密 X
R15 = R0R_0603_5%: RES,0R,1/10W,5%,R0603; Part Number: 30304091; Manufacture 1: 风华高科FH; Manufacture 1 P/N: RS03K000JT; 代理/分销商: 四平市吉华高新技术有限公司; 元件名称: 贴片电阻 0Ω-0603
R18 R21 = NC_R0603: NC,R0603
R19 = R10K_0402_5%_X: RES,10K,1/16W,5%,R0402; Part Number: 30304345; Manufacture 1: YAGEO; Manufacture 1 P/N: RC0402JR-0710KL; 代理/分销商: 厦门信和达电子有限公司; 元件名称: 贴片电阻10K-0402
R20 = R100K_0603_1%_X: RES,100K,1/10W,1%,R0603; Part Number: 30304402; Manufacture 1: YAGEO; Manufacture 1 P/N: RC0603FR-07100KL; 代理/分销商: 厦门信和达电子有限公司; 元件名称: 贴片电阻100K-0603-精密 X
R22 = R330R_0805_5%_X: RES,330R,1/8W,5%,R0805; Part Number: 30304618; Manufacture 1: YAGEO; Manufacture 1 P/N: RC0805JR-07330RL; 代理/分销商: 厦门信和达电子有限公司
R24 = R1K_0402_5%_X: RES,1K,1/16W,5%,R0402; Part Number: 30304346; Manufacture 1: YAGEO; Manufacture 1 P/N: RC0402JR-071KL; 代理/分销商: 厦门信和达电子有限公司
R25 = R10K_0402_5%_X: RES,10K,1/16W,5%,R0402; Part Number: 30304345; Manufacture 1: YAGEO; Manufacture 1 P/N: RC0402JR-0710KL; 代理/分销商: 厦门信和达电子有限公司
TP13 TP14 = 1.0测试点: 测试点 Φ1.0mm
U2 = R7F7016843: IC,R7F7016843AFP-C,MCU,CPU Frequency 120MHz max,Code Flash 1024KB,Data Flash 64KB,Local RAM (LRAM)96KB,Retention RAM (RRAM)32KB,Trace RAM 32KB,Renesas,LQFP100,14x14x1.7mm,-40℃ to 105℃
Y1 = DSX321G-8M: Crystal,8MHz,10.0pF,SMD,3.2x2.5x1mm; Part Number: 30308005; Manufacture 1: KDS; Manufacture 1 P/N: DSX321G 1C208000CE0AF; 代理/分销商: 大连嘉誉科技有限公司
